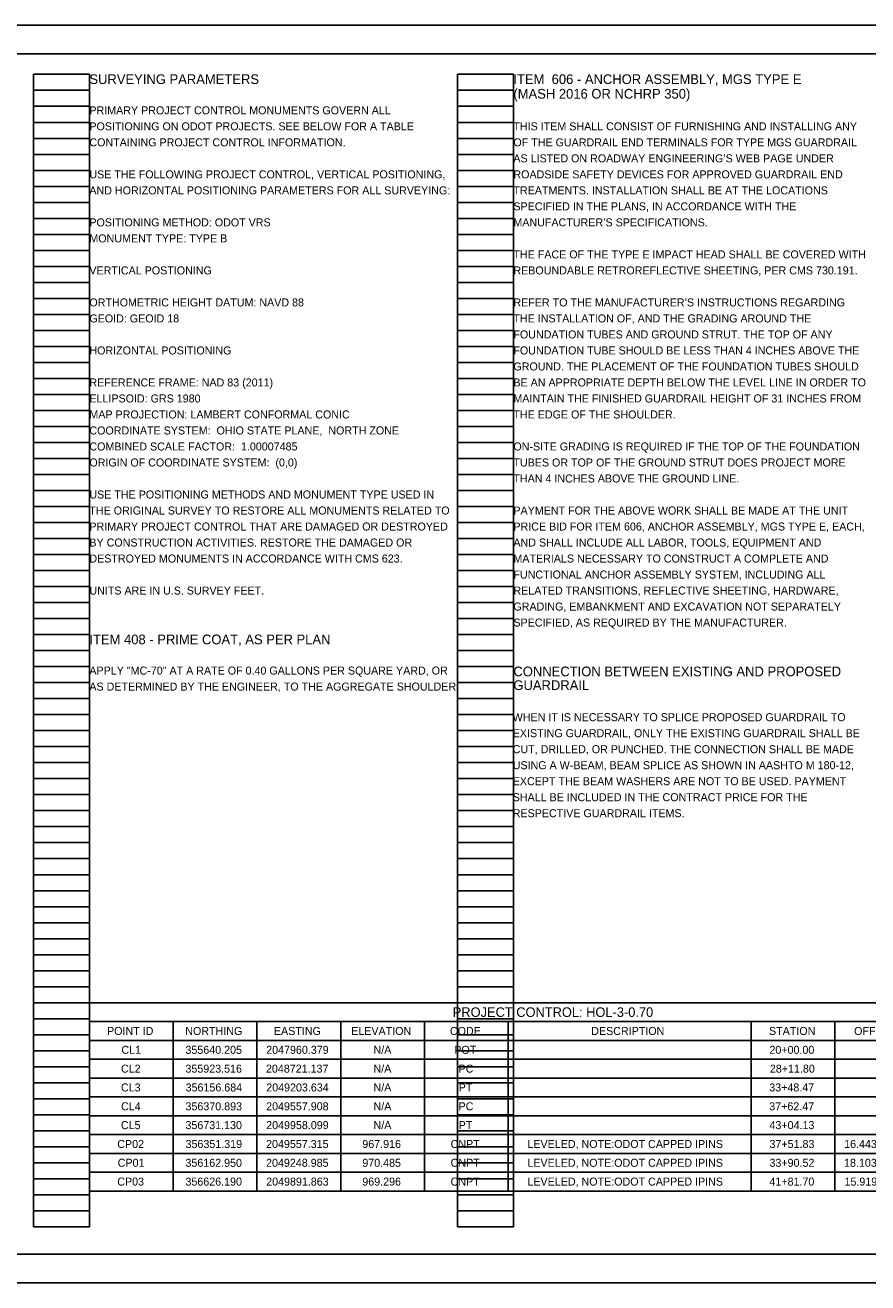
# Model space of a CAD drawing. Extents: x -7.6 to 34, y 0 to 22.
# Drawn here: x 8.7 to 23.44, y 0 to 22 of the extents above; entities that cross this region are included whole.
import ezdxf

# ---------------------------------------------------------------- set-up
doc = ezdxf.new("R2010")
doc.units = 0
for name, color, linetype in [('SH_Border', 7, 'Continuous'), ('SH_Cut_Line', 7, 'Continuous'), ('SH_Data', 7, 'Continuous'), ('SH_Text', 7, 'Continuous')]:
    doc.layers.add(name, color=color, linetype=linetype)

msp = doc.modelspace()

# ---------------------------------------------------------------- linework, layer by layer
at = {"layer": 'SH_Border'}
msp.add_lwpolyline([(1.5, 21.5), (33.5, 21.5), (33.5, 0.5), (1.5, 0.5)], close=True, dxfattribs=at)
at = {"layer": 'SH_Cut_Line'}
msp.add_lwpolyline([(0, 0), (34, 0), (34, 22), (0, 22)], close=True, dxfattribs=at)
at = {"layer": 'SH_Data'}
for p, q in [((8.84, 0.98), (8.84, 21.14)), ((8.84, 21.14), (9.82, 21.14)), ((9.82, 0.98), (9.82, 21.14)), ((16.26, 0.98), (16.26, 21.14)), ((16.26, 21.14), (17.24, 21.14)), ((17.24, 0.98), (17.24, 21.14)), ((8.84, 20.86), (9.82, 20.86)), ((16.26, 20.86), (17.24, 20.86)), ((8.84, 20.58), (9.82, 20.58)), ((16.26, 20.58), (17.24, 20.58)), ((8.84, 20.3), (9.82, 20.3)), ((16.26, 20.3), (17.24, 20.3)), ((8.84, 20.02), (9.82, 20.02)), ((16.26, 20.02), (17.24, 20.02)), ((8.84, 19.74), (9.82, 19.74)), ((16.26, 19.74), (17.24, 19.74)), ((8.84, 19.46), (9.82, 19.46)), ((16.26, 19.46), (17.24, 19.46)), ((8.84, 19.18), (9.82, 19.18)), ((16.26, 19.18), (17.24, 19.18)), ((8.84, 18.9), (9.82, 18.9)), ((16.26, 18.9), (17.24, 18.9)), ((8.84, 18.62), (9.82, 18.62)), ((16.26, 18.62), (17.24, 18.62)), ((8.84, 18.34), (9.82, 18.34)), ((16.26, 18.34), (17.24, 18.34)), ((8.84, 18.06), (9.82, 18.06)), ((16.26, 18.06), (17.24, 18.06)), ((8.84, 17.78), (9.82, 17.78)), ((16.26, 17.78), (17.24, 17.78)), ((8.84, 17.5), (9.82, 17.5)), ((16.26, 17.5), (17.24, 17.5)), ((8.84, 17.22), (9.82, 17.22)), ((16.26, 17.22), (17.24, 17.22)), ((8.84, 16.94), (9.82, 16.94)), ((16.26, 16.94), (17.24, 16.94)), ((8.84, 16.66), (9.82, 16.66)), ((16.26, 16.66), (17.24, 16.66)), ((8.84, 16.38), (9.82, 16.38)), ((16.26, 16.38), (17.24, 16.38)), ((8.84, 16.1), (9.82, 16.1)), ((16.26, 16.1), (17.24, 16.1)), ((8.84, 15.82), (9.82, 15.82)), ((16.26, 15.82), (17.24, 15.82)), ((8.84, 15.54), (9.82, 15.54)), ((16.26, 15.54), (17.24, 15.54)), ((8.84, 15.26), (9.82, 15.26)), ((16.26, 15.26), (17.24, 15.26)), ((8.84, 14.98), (9.82, 14.98)), ((16.26, 14.98), (17.24, 14.98)), ((8.84, 14.7), (9.82, 14.7)), ((16.26, 14.7), (17.24, 14.7)), ((8.84, 14.42), (9.82, 14.42)), ((16.26, 14.42), (17.24, 14.42)), ((8.84, 14.14), (9.82, 14.14)), ((16.26, 14.14), (17.24, 14.14)), ((8.84, 13.86), (9.82, 13.86)), ((16.26, 13.86), (17.24, 13.86)), ((8.84, 13.58), (9.82, 13.58)), ((16.26, 13.58), (17.24, 13.58)), ((8.84, 13.3), (9.82, 13.3)), ((16.26, 13.3), (17.24, 13.3)), ((8.84, 13.02), (9.82, 13.02)), ((16.26, 13.02), (17.24, 13.02)), ((8.84, 12.74), (9.82, 12.74)), ((16.26, 12.74), (17.24, 12.74)), ((8.84, 12.46), (9.82, 12.46)), ((16.26, 12.46), (17.24, 12.46)), ((8.84, 12.18), (9.82, 12.18)), ((16.26, 12.18), (17.24, 12.18)), ((8.84, 11.9), (9.82, 11.9)), ((16.26, 11.9), (17.24, 11.9)), ((8.84, 11.62), (9.82, 11.62)), ((16.26, 11.62), (17.24, 11.62)), ((8.84, 11.34), (9.82, 11.34)), ((16.26, 11.34), (17.24, 11.34)), ((8.84, 11.06), (9.82, 11.06)), ((16.26, 11.06), (17.24, 11.06)), ((8.84, 10.78), (9.82, 10.78)), ((16.26, 10.78), (17.24, 10.78)), ((8.84, 10.5), (9.82, 10.5)), ((16.26, 10.5), (17.24, 10.5)), ((8.84, 10.22), (9.82, 10.22)), ((16.26, 10.22), (17.24, 10.22)), ((8.84, 9.94), (9.82, 9.94)), ((16.26, 9.94), (17.24, 9.94)), ((8.84, 9.66), (9.82, 9.66)), ((16.26, 9.66), (17.24, 9.66)), ((8.84, 9.38), (9.82, 9.38)), ((16.26, 9.38), (17.24, 9.38)), ((8.84, 9.1), (9.82, 9.1)), ((16.26, 9.1), (17.24, 9.1)), ((8.84, 8.82), (9.82, 8.82)), ((16.26, 8.82), (17.24, 8.82)), ((8.84, 8.54), (9.82, 8.54)), ((16.26, 8.54), (17.24, 8.54)), ((8.84, 8.26), (9.82, 8.26)), ((16.26, 8.26), (17.24, 8.26)), ((8.84, 7.98), (9.82, 7.98)), ((16.26, 7.98), (17.24, 7.98)), ((8.84, 7.7), (9.82, 7.7)), ((16.26, 7.7), (17.24, 7.7)), ((8.84, 7.42), (9.82, 7.42)), ((16.26, 7.42), (17.24, 7.42)), ((8.84, 7.14), (9.82, 7.14)), ((16.26, 7.14), (17.24, 7.14)), ((8.84, 6.86), (9.82, 6.86)), ((16.26, 6.86), (17.24, 6.86)), ((8.84, 6.58), (9.82, 6.58)), ((16.26, 6.58), (17.24, 6.58)), ((8.84, 6.3), (9.82, 6.3)), ((16.26, 6.3), (17.24, 6.3)), ((8.84, 6.02), (9.82, 6.02)), ((16.26, 6.02), (17.24, 6.02)), ((8.84, 5.74), (9.82, 5.74)), ((16.26, 5.74), (17.24, 5.74)), ((8.84, 5.46), (9.82, 5.46)), ((16.26, 5.46), (17.24, 5.46)), ((8.84, 5.18), (9.82, 5.18)), ((16.26, 5.18), (17.24, 5.18)), ((8.84, 4.9), (9.82, 4.9)), ((16.26, 4.9), (17.24, 4.9)), ((8.84, 4.62), (9.82, 4.62)), ((16.26, 4.62), (17.24, 4.62)), ((8.84, 4.34), (9.82, 4.34)), ((16.26, 4.34), (17.24, 4.34)), ((8.84, 4.06), (9.82, 4.06)), ((16.26, 4.06), (17.24, 4.06)), ((8.84, 3.78), (9.82, 3.78)), ((16.26, 3.78), (17.24, 3.78)), ((8.84, 3.5), (9.82, 3.5)), ((16.26, 3.5), (17.24, 3.5)), ((8.84, 3.22), (9.82, 3.22)), ((16.26, 3.22), (17.24, 3.22)), ((8.84, 2.94), (9.82, 2.94)), ((16.26, 2.94), (17.24, 2.94)), ((8.84, 2.66), (9.82, 2.66)), ((16.26, 2.66), (17.24, 2.66)), ((8.84, 2.38), (9.82, 2.38)), ((16.26, 2.38), (17.24, 2.38)), ((8.84, 2.1), (9.82, 2.1)), ((16.26, 2.1), (17.24, 2.1)), ((8.84, 1.82), (9.82, 1.82)), ((16.26, 1.82), (17.24, 1.82)), ((8.84, 1.54), (9.82, 1.54)), ((16.26, 1.54), (17.24, 1.54)), ((8.84, 1.26), (9.82, 1.26)), ((16.26, 1.26), (17.24, 1.26)), ((8.84, 0.98), (9.82, 0.98)), ((16.26, 0.98), (17.24, 0.98))]:
    msp.add_line(p, q, dxfattribs=at)
at = {"layer": 'SH_Text'}
for p, q in [((9.82, 4.9), (26.258, 4.9)), ((9.82, 4.9), (9.82, 1.606)), ((9.82, 4.571), (26.258, 4.571)), ((11.286, 4.571), (11.286, 1.606)), ((12.752, 4.571), (12.752, 1.606)), ((14.218, 4.571), (14.218, 1.606)), ((15.684, 4.571), (15.684, 1.606)), ((17.149, 4.571), (17.149, 1.606)), ((21.399, 4.571), (21.399, 1.606)), ((22.865, 4.571), (22.865, 1.606)), ((9.82, 4.241), (26.258, 4.241)), ((9.82, 3.912), (26.258, 3.912)), ((9.82, 3.582), (26.258, 3.582)), ((9.82, 3.253), (26.258, 3.253)), ((9.82, 2.924), (26.258, 2.924)), ((9.82, 2.594), (26.258, 2.594)), ((9.82, 2.265), (26.258, 2.265)), ((9.82, 1.935), (26.258, 1.935)), ((9.82, 1.606), (26.258, 1.606))]:
    msp.add_line(p, q, dxfattribs=at)

# ---------------------------------------------------------------- texts
for s, height, p in [('SURVEYING PARAMETERS', 0.17, (9.82, 20.97)), ('ITEM  606 - ANCHOR ASSEMBLY, MGS TYPE E', 0.17, (17.24, 20.97)), ('(MASH 2016 OR NCHRP 350)', 0.17, (17.24, 20.715)), ('PRIMARY PROJECT CONTROL MONUMENTS GOVERN ALL ', 0.14, (9.82, 20.44)), ('POSITIONING ON ODOT PROJECTS. SEE BELOW FOR A TABLE ', 0.14, (9.82, 20.16)), ('THIS ITEM SHALL CONSIST OF FURNISHING AND INSTALLING ANY ', 0.14, (17.24, 20.16)), ('CONTAINING PROJECT CONTROL INFORMATION.', 0.14, (9.82, 19.88)), ('OF THE GUARDRAIL END TERMINALS FOR TYPE MGS GUARDRAIL ', 0.14, (17.24, 19.88)), ('AS LISTED ON ROADWAY ENGINEERING’S WEB PAGE UNDER ', 0.14, (17.24, 19.6)), ('USE THE FOLLOWING PROJECT CONTROL, VERTICAL POSITIONING, ', 0.14, (9.82, 19.32)), ('ROADSIDE SAFETY DEVICES FOR APPROVED GUARDRAIL END ', 0.14, (17.24, 19.32)), ('AND HORIZONTAL POSITIONING PARAMETERS FOR ALL SURVEYING:', 0.14, (9.82, 19.04)), ('TREATMENTS. INSTALLATION SHALL BE AT THE LOCATIONS ', 0.14, (17.24, 19.04)), ('SPECIFIED IN THE PLANS, IN ACCORDANCE WITH THE ', 0.14, (17.24, 18.76)), ('POSITIONING METHOD: ODOT VRS', 0.14, (9.82, 18.48)), ('MANUFACTURER’S SPECIFICATIONS.', 0.14, (17.24, 18.48)), ('MONUMENT TYPE: TYPE B', 0.14, (9.82, 18.2)), ('THE FACE OF THE TYPE E IMPACT HEAD SHALL BE COVERED WITH ', 0.14, (17.24, 17.92)), ('VERTICAL POSTIONING', 0.14, (9.82, 17.64)), ('REBOUNDABLE RETROREFLECTIVE SHEETING, PER CMS 730.191.', 0.14, (17.24, 17.64)), ('ORTHOMETRIC HEIGHT DATUM: NAVD 88', 0.14, (9.82, 17.08)), ('REFER TO THE MANUFACTURER’S INSTRUCTIONS REGARDING ', 0.14, (17.24, 17.08)), ('GEOID: GEOID 18', 0.14, (9.82, 16.8)), ('THE INSTALLATION OF, AND THE GRADING AROUND THE ', 0.14, (17.24, 16.8)), ('FOUNDATION TUBES AND GROUND STRUT. THE TOP OF ANY ', 0.14, (17.24, 16.52)), ('HORIZONTAL POSITIONING', 0.14, (9.82, 16.24)), ('FOUNDATION TUBE SHOULD BE LESS THAN 4 INCHES ABOVE THE ', 0.14, (17.24, 16.24)), ('GROUND. THE PLACEMENT OF THE FOUNDATION TUBES SHOULD ', 0.14, (17.24, 15.96)), ('REFERENCE FRAME: NAD 83 (2011)', 0.14, (9.82, 15.68)), ('BE AN APPROPRIATE DEPTH BELOW THE LEVEL LINE IN ORDER TO ', 0.14, (17.24, 15.68)), ('ELLIPSOID: GRS 1980', 0.14, (9.82, 15.4)), ('MAINTAIN THE FINISHED GUARDRAIL HEIGHT OF 31 INCHES FROM ', 0.14, (17.24, 15.4)), ('MAP PROJECTION: LAMBERT CONFORMAL CONIC', 0.14, (9.82, 15.12)), ('THE EDGE OF THE SHOULDER.', 0.14, (17.24, 15.12)), ('COORDINATE SYSTEM:  OHIO STATE PLANE,  NORTH ZONE', 0.14, (9.82, 14.84)), ('COMBINED SCALE FACTOR:  1.00007485', 0.14, (9.82, 14.56)), ('ON-SITE GRADING IS REQUIRED IF THE TOP OF THE FOUNDATION ', 0.14, (17.24, 14.56)), ('ORIGIN OF COORDINATE SYSTEM:  (0,0)', 0.14, (9.82, 14.28)), ('TUBES OR TOP OF THE GROUND STRUT DOES PROJECT MORE ', 0.14, (17.24, 14.28)), ('THAN 4 INCHES ABOVE THE GROUND LINE.', 0.14, (17.24, 14)), ('USE THE POSITIONING METHODS AND MONUMENT TYPE USED IN ', 0.14, (9.82, 13.72)), ('THE ORIGINAL SURVEY TO RESTORE ALL MONUMENTS RELATED TO ', 0.14, (9.82, 13.44)), ('PAYMENT FOR THE ABOVE WORK SHALL BE MADE AT THE UNIT ', 0.14, (17.24, 13.44)), ('PRIMARY PROJECT CONTROL THAT ARE DAMAGED OR DESTROYED ', 0.14, (9.82, 13.16)), ('PRICE BID FOR ITEM 606, ANCHOR ASSEMBLY, MGS TYPE E, EACH, ', 0.14, (17.24, 13.16)), ('BY CONSTRUCTION ACTIVITIES. RESTORE THE DAMAGED OR ', 0.14, (9.82, 12.88)), ('AND SHALL INCLUDE ALL LABOR, TOOLS, EQUIPMENT AND ', 0.14, (17.24, 12.88)), ('DESTROYED MONUMENTS IN ACCORDANCE WITH CMS 623.', 0.14, (9.82, 12.6)), ('MATERIALS NECESSARY TO CONSTRUCT A COMPLETE AND ', 0.14, (17.24, 12.6)), ('FUNCTIONAL ANCHOR ASSEMBLY SYSTEM, INCLUDING ALL ', 0.14, (17.24, 12.32)), ('UNITS ARE IN U.S. SURVEY FEET.', 0.14, (9.82, 12.04)), ('RELATED TRANSITIONS, REFLECTIVE SHEETING, HARDWARE, ', 0.14, (17.24, 12.04)), ('GRADING, EMBANKMENT AND EXCAVATION NOT SEPARATELY ', 0.14, (17.24, 11.76)), ('SPECIFIED, AS REQUIRED BY THE MANUFACTURER.', 0.14, (17.24, 11.48)), ('ITEM 408 - PRIME COAT, AS PER PLAN', 0.17, (9.82, 11.17)), ('APPLY "MC-70" AT A RATE OF 0.40 GALLONS PER SQUARE YARD, OR ', 0.14, (9.82, 10.64)), ('CONNECTION BETWEEN EXISTING AND PROPOSED ', 0.17, (17.24, 10.61)), ('AS DETERMINED BY THE ENGINEER, TO THE AGGREGATE SHOULDER.', 0.14, (9.82, 10.36)), ('GUARDRAIL', 0.17, (17.24, 10.37)), ('WHEN IT IS NECESSARY TO SPLICE PROPOSED GUARDRAIL TO ', 0.14, (17.228, 9.825)), ('EXISTING GUARDRAIL, ONLY THE EXISTING GUARDRAIL SHALL BE ', 0.14, (17.228, 9.545)), ('CUT, DRILLED, OR PUNCHED. THE CONNECTION SHALL BE MADE ', 0.14, (17.228, 9.265)), ('USING A W-BEAM, BEAM SPLICE AS SHOWN IN AASHTO M 180-12, ', 0.14, (17.228, 8.985)), ('EXCEPT THE BEAM WASHERS ARE NOT TO BE USED. PAYMENT ', 0.14, (17.228, 8.705)), ('SHALL BE INCLUDED IN THE CONTRACT PRICE FOR THE ', 0.14, (17.228, 8.425)), ('RESPECTIVE GUARDRAIL ITEMS.', 0.14, (17.228, 8.145)), ('PROJECT CONTROL: HOL-3-0.70', 0.168, (16.179, 4.651)), ('POINT ID', 0.14, (10.129, 4.336)), ('NORTHING', 0.14, (11.498, 4.336)), ('EASTING', 0.14, (13.049, 4.336)), ('ELEVATION', 0.14, (14.401, 4.336)), ('CODE', 0.14, (16.129, 4.336)), ('DESCRIPTION', 0.14, (18.602, 4.336)), ('STATION', 0.14, (21.713, 4.336)), ('OFFSET', 0.14, (23.202, 4.336)), ('CL1', 0.14, (10.381, 4.006)), ('355640.205', 0.14, (11.501, 4.006)), ('2047960.379', 0.14, (12.914, 4.006)), ('N/A', 0.14, (14.792, 4.006)), ('POT', 0.14, (16.206, 4.006)), ('20+00.00', 0.14, (21.72, 4.006)), ('CL2', 0.14, (10.373, 3.677)), ('355923.516', 0.14, (11.501, 3.677)), ('2048721.137', 0.14, (12.91, 3.677)), ('N/A', 0.14, (14.792, 3.677)), ('PC', 0.14, (16.28, 3.677)), ('28+11.80', 0.14, (21.728, 3.677)), ('CL3', 0.14, (10.373, 3.348)), ('356156.684', 0.14, (11.504, 3.348)), ('2049203.634', 0.14, (12.915, 3.348)), ('N/A', 0.14, (14.792, 3.348)), ('PT', 0.14, (16.282, 3.348)), ('33+48.47', 0.14, (21.717, 3.348)), ('CL4', 0.14, (10.375, 3.018)), ('356370.893', 0.14, (11.502, 3.018)), ('2049557.908', 0.14, (12.913, 3.018)), ('N/A', 0.14, (14.792, 3.018)), ('PC', 0.14, (16.28, 3.018)), ('37+62.47', 0.14, (21.717, 3.018)), ('CL5', 0.14, (10.372, 2.689)), ('356731.130', 0.14, (11.501, 2.689)), ('2049958.099', 0.14, (12.914, 2.689)), ('N/A', 0.14, (14.792, 2.689)), ('PT', 0.14, (16.282, 2.689)), ('43+04.13', 0.14, (21.721, 2.689)), ('CP02', 0.14, (10.308, 2.359)), ('356351.319', 0.14, (11.503, 2.359)), ('2049557.315', 0.14, (12.912, 2.359)), ('967.916', 0.14, (14.596, 2.359)), ('CNPT', 0.14, (16.141, 2.359)), ('LEVELED, NOTE:ODOT CAPPED IPINS', 0.14, (17.485, 2.359)), ('37+51.83', 0.14, (21.721, 2.359)), ('16.44391774', 0.14, (23.028, 2.359)), ('CP01', 0.14, (10.316, 2.03)), ('356162.950', 0.14, (11.501, 2.03)), ('2049248.985', 0.14, (12.912, 2.03)), ('970.485', 0.14, (14.596, 2.03)), ('CNPT', 0.14, (16.141, 2.03)), ('LEVELED, NOTE:ODOT CAPPED IPINS', 0.14, (17.485, 2.03)), ('33+90.52', 0.14, (21.721, 2.03)), ('18.10312922', 0.14, (23.026, 2.03)), ('CP03', 0.14, (10.308, 1.701)), ('356626.190', 0.14, (11.501, 1.701)), ('2049891.863', 0.14, (12.914, 1.701)), ('969.296', 0.14, (14.596, 1.701)), ('CNPT', 0.14, (16.141, 1.701)), ('LEVELED, NOTE:ODOT CAPPED IPINS', 0.14, (17.485, 1.701)), ('41+81.70', 0.14, (21.72, 1.701)), ('15.91904991', 0.14, (23.034, 1.701))]:
    msp.add_text(s, height=height, dxfattribs=at).set_placement(p)

doc.saveas('drawing.dxf')
